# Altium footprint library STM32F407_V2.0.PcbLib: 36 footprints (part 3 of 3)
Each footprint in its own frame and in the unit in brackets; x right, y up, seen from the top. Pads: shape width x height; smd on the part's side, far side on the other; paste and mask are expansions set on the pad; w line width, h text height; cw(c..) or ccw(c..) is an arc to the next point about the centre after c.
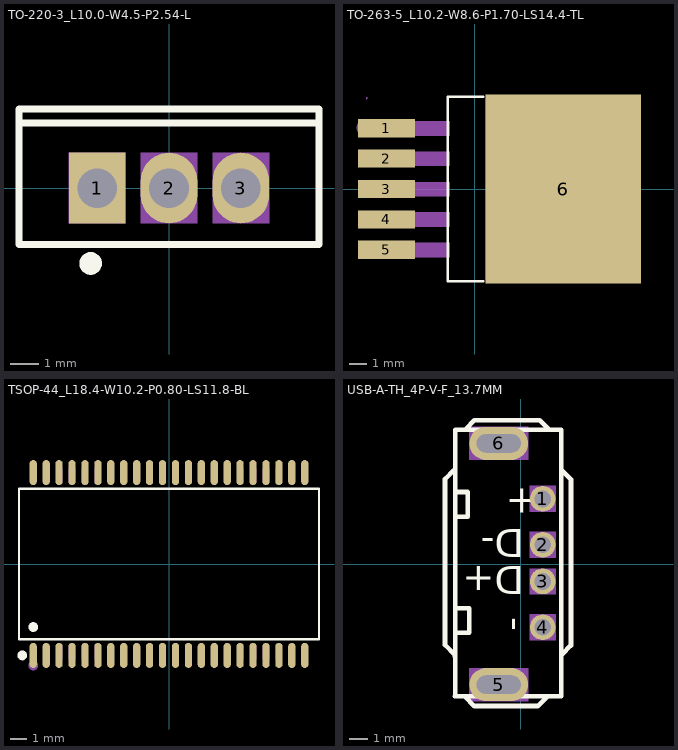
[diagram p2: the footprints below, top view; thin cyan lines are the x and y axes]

## TO-220-3_L10.0-W4.5-P2.54-L [mm]
pads (3):
  rect 2x2.5 hole 1.4: 1(-2.54,0)
  oval 2x2.5 hole 1.4: 2(0,0) 3(2.54,0)
Top Overlay:
  lines w0.254: -5.3,2.3 5.3,2.3 ; -5.301,-1.999 -5.301,2.794 -5.301,2.799 5.301,2.799 5.301,-1.999 -5.301,-1.999
  lines w0.4: -2.769,-2.464 ccw(c-2.767,-2.664) -2.766,-2.464
Mechanical 5:
  region: -3.541,1.25 -1.539,1.25 -1.539,-1.25 -3.541,-1.25
  region: 1.54,1.25 3.54,1.25 3.54,-1.25 1.54,-1.25
  region: -1,1.25 1,1.25 1,-1.25 -1,-1.25

## TO-263-5_L10.2-W8.6-P1.70-LS14.4-TL [mm]
pads (6):
  rect 3.183x1.02 smd: 1(-4.953,3.4) 2(-4.953,1.7) 3(-4.953,0) 4(-4.953,-1.7) 5(-4.953,-3.4)
  rect 8.705x10.587 smd: 6(4.953,0)
Top Overlay:
  lines w0.152: 0.448,-5.166 -1.516,-5.166 -1.516,5.166 0.448,5.166
Mechanical 5:
  region: -6.096,2.995 -6.096,3.805 -4.056,3.805 -4.056,2.995
  region: -6.096,1.295 -6.096,2.105 -4.056,2.105 -4.056,1.295
  region: -6.096,-0.405 -6.096,0.405 -4.056,0.405 -4.056,-0.405
  region: -6.096,-2.105 -6.096,-1.295 -4.056,-1.295 -4.056,-2.105
  region: -6.096,-3.81 -6.096,-3 -4.056,-3 -4.056,-3.81
  region: 0.6,-5.09 0.6,5.09 7.552,5.09 8.57,4.072 8.57,-4.072 7.552,-5.09
  pour cut-out: -4.096,-3.81 -4.096,-3.01 -1.396,-3.01 -1.396,-3.81
  pour cut-out: -4.096,-2.11 -4.096,-1.31 -1.396,-1.31 -1.396,-2.11
  pour cut-out: -4.096,-0.41 -4.096,0.39 -1.396,0.39 -1.396,-0.41
  pour cut-out: -4.096,1.29 -4.096,2.09 -1.396,2.09 -1.396,1.29
  pour cut-out: -4.096,2.99 -4.096,3.79 -1.396,3.79 -1.396,2.99
Mechanical 6:
  circle w0.06: c-6.066,5.09 r0.03
Mechanical 15:
  circle w0.4: c-6.223,3.429 r0.2

## TSOP-44_L18.4-W10.2-P0.80-LS11.8-BL [mm]
pads (44):
  oval 0.448x1.551 smd: 1(-8.4,-5.655) 2(-7.6,-5.655) 3(-6.8,-5.655) 4(-6,-5.655) 5(-5.2,-5.655) 6(-4.4,-5.655) 7(-3.6,-5.655) 8(-2.8,-5.655) 9(-2,-5.655) 10(-1.2,-5.655) 11(-0.4,-5.655) 12(0.4,-5.655) 13(1.2,-5.655) 14(2,-5.655) 15(2.8,-5.655) 16(3.6,-5.655) 17(4.4,-5.655) 18(5.2,-5.655) 19(6,-5.655) 20(6.8,-5.655) 21(7.6,-5.655) 22(8.4,-5.655) 23(8.4,5.655) 24(7.6,5.655) 25(6.8,5.655) 26(6,5.655) 27(5.2,5.655) 28(4.4,5.655) 29(3.6,5.655) 30(2.8,5.655) 31(2,5.655) 32(1.2,5.655) 33(0.4,5.655) 34(-0.4,5.655) 35(-1.2,5.655) 36(-2,5.655) 37(-2.8,5.655) 38(-3.6,5.655) 39(-4.4,5.655) 40(-5.2,5.655) 41(-6,5.655) 42(-6.8,5.655) 43(-7.6,5.655) 44(-8.4,5.655)
Top Overlay:
  circle w0.3: c-8.4,-3.899 r0.15
  circle w0.3: c-9.076,-5.656 r0.15
  lines w0.152: -9.281,-4.651 -9.281,4.651 9.281,4.651 9.281,-4.651 -9.281,-4.651
Mechanical 5:
  drawing of 88 lines, arcs and shapes, not listed
Mechanical 6:
  circle w0.06: c-9.205,-5.88 r0.03
Mechanical 15:
  circle w0.3: c-8.4,-6.28 r0.15

## USB-A-TH_4P-V-F_13.7MM [mm]
pads (6):
  round 1.4 hole 0.92: 1(1.2,3.551) 2(1.2,1.052) 3(1.2,-0.947) 4(1.2,-3.447)
  oval 3.2x1.8 hole 1 slot 2.4 at 0 deg: 5(-1.2,-6.571) 6(-1.2,6.571)
Top Overlay:
  lines w0.254: -3.64,5.114 -4.123,4.631 -4.123,-4.411 -3.589,-4.944 -3.589,-5.046 ; -3.594,-7.196 2.206,-7.196 2.206,7.307 ; -3.564,-7.193 -3.564,7.307 2.206,7.307 ; -3.538,2.574 -3.386,2.574 -2.878,2.574 -2.878,3.92 -3.538,3.92 ; -3.462,-3.751 -3.31,-3.751 -2.802,-3.751 -2.802,-2.404 -3.462,-2.404 ; -3.056,-7.205 -2.522,-7.738 0.932,-7.738 1.465,-7.205 ; -3.005,7.349 -2.522,7.832 1.034,7.832 1.558,7.307 2.206,7.307 ; 2.202,5.241 2.202,5.139 2.735,4.606 2.735,-4.436 2.253,-4.919
  text "+" at -0.821,2.803 h1.52
  text "D-" at 0.202,1.905 h1.52
  text "D+" at 0.202,-0.127 h1.52
  text "-" at -0.948,-2.912 h1.52
Mechanical 5:
  region: 0.5,-0.247 1.9,-0.247 1.9,-1.647 0.5,-1.647
  region: 0.5,1.752 1.9,1.752 1.9,0.352 0.5,0.352
  region: 0.5,-2.747 1.9,-2.747 1.9,-4.147 0.5,-4.147
  region: 0.5,4.251 1.9,4.251 1.9,2.851 0.5,2.851
  region: -2.8,-5.671 0.4,-5.671 0.4,-7.471 -2.8,-7.471
  region: -2.8,7.471 0.4,7.471 0.4,5.671 -2.8,5.671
